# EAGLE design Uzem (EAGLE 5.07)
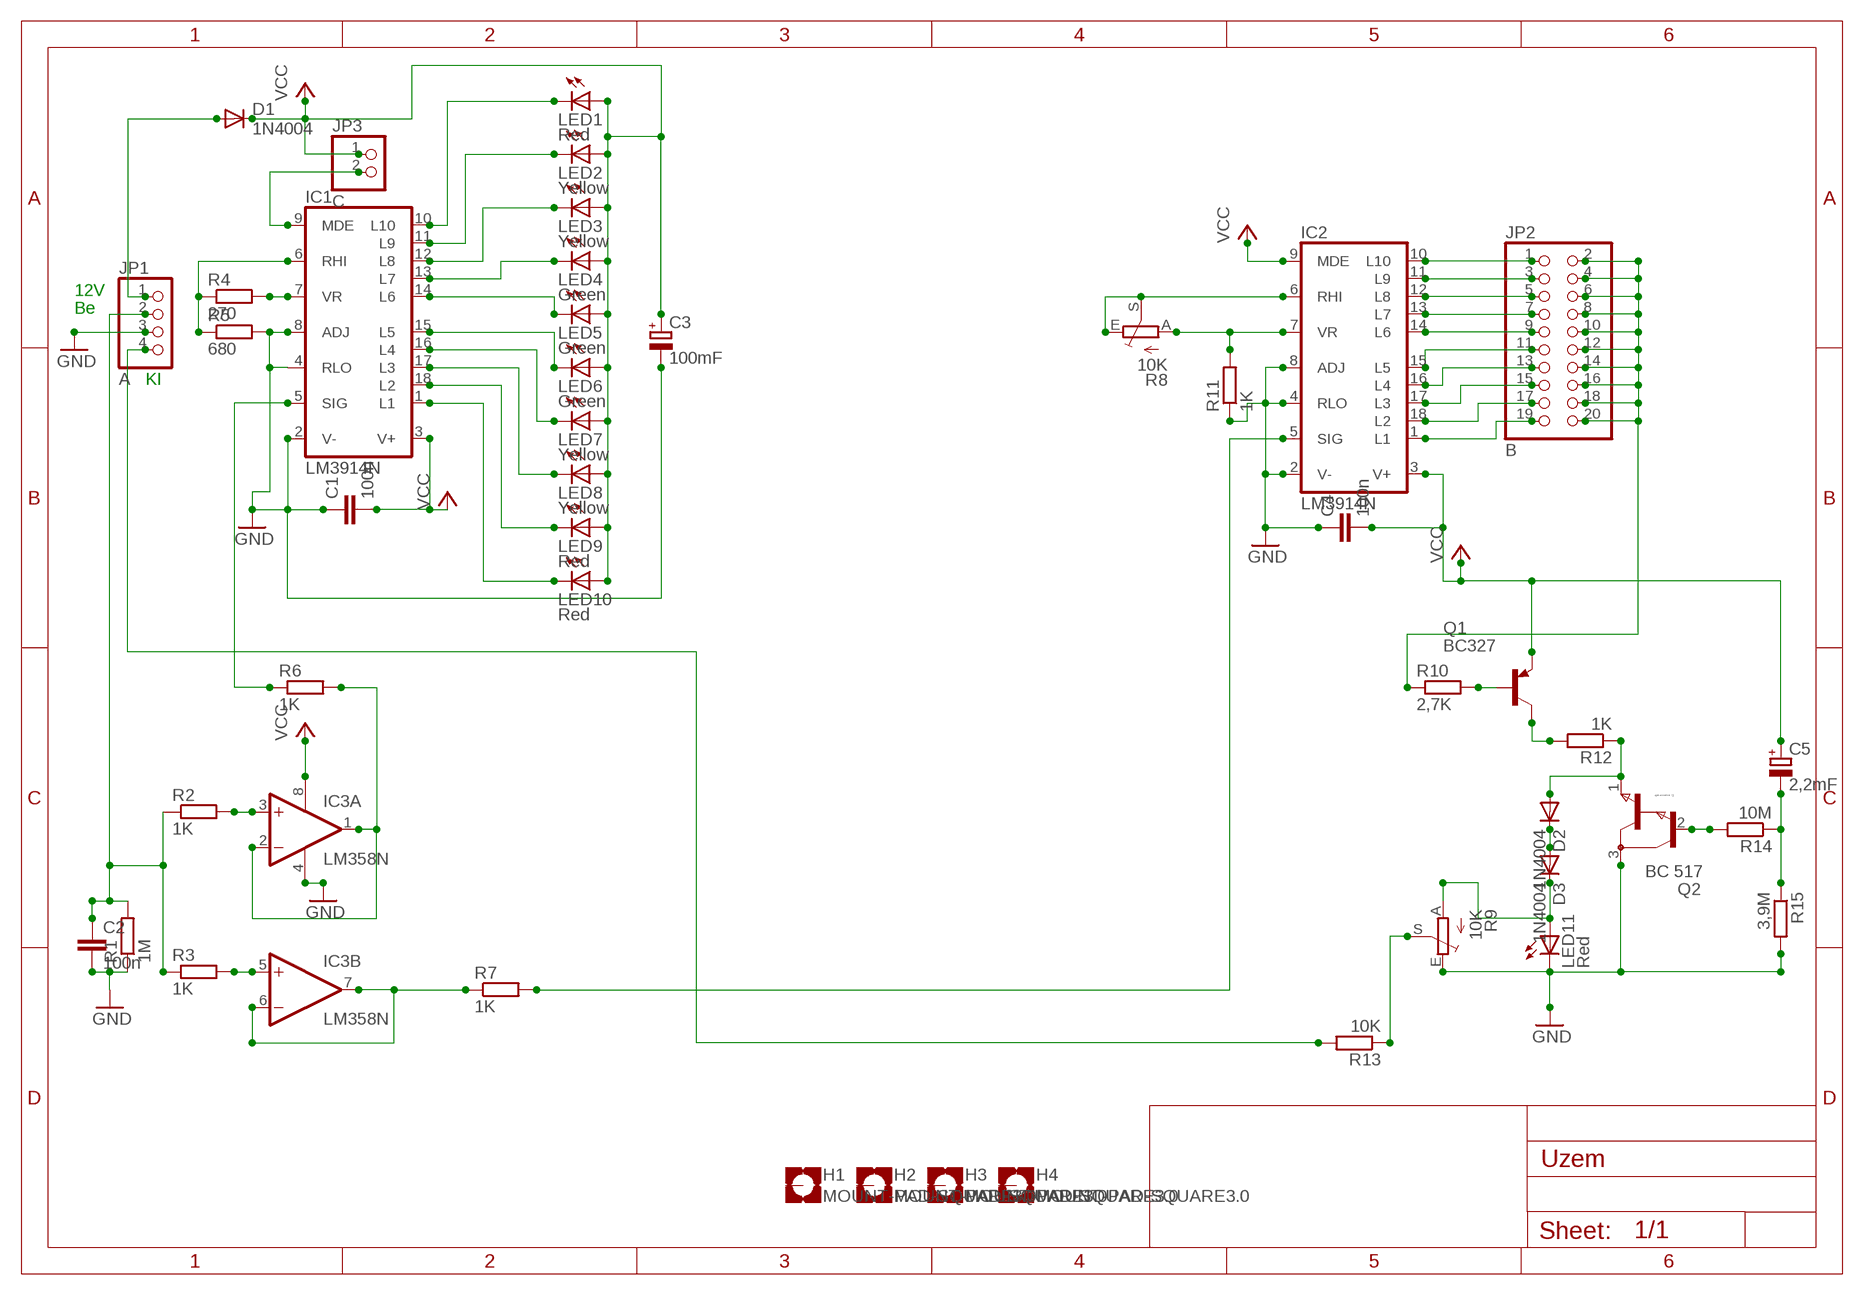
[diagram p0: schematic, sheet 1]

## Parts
C1  100n  C-EU025-025X050  [C025-025X050]
C2  100n  C-EU025-025X050  [C025-025X050]
C3  100mF  CPOL-EUE2,5-6E  [E2,5-6E]
C4  100n  C-EU025-025X050  [C025-025X050]
C5  2,2mF  CPOL-EUE2,5-6E  [E2,5-6E]
D1  1N4004  [DO41-10]
D2  1N4004  [DO41-10]
D3  1N4004  [DO41-10]
H1  MOUNT-PAD-SQUARE3.0  [3,0-PAD-SQUARE]
H2  MOUNT-PAD-SQUARE3.0  [3,0-PAD-SQUARE]
H3  MOUNT-PAD-SQUARE3.0  [3,0-PAD-SQUARE]
H4  MOUNT-PAD-SQUARE3.0  [3,0-PAD-SQUARE]
IC1  LM3914N  [DIL18]
IC2  LM3914N  [DIL18]
IC3  LM358N  [DIL08]
JP1  A  PINHD-1X4  [1X04]
JP2  B  PINHD-2X10  [2X10]
JP3  C  PINHD-1X2  [1X02]
LED1  Red  LED5MM  [LED5MM]
LED2  Yellow  LED5MM  [LED5MM]
LED3  Yellow  LED5MM  [LED5MM]
LED4  Green  LED5MM  [LED5MM]
LED5  Green  LED5MM  [LED5MM]
LED6  Green  LED5MM  [LED5MM]
LED7  Yellow  LED5MM  [LED5MM]
LED8  Yellow  LED5MM  [LED5MM]
LED9  Red  LED5MM  [LED5MM]
LED10  Red  LED5MM  [LED5MM]
LED11  Red  LED5MM  [LED5MM]
Q1  BC327  [TO92]
Q2  BC 517  BC517  [TO92]
R1  1M  R-EU_0204/7  [0204/7]
R2  1K  R-EU_0204/7  [0204/7]
R3  1K  R-EU_0204/7  [0204/7]
R4  270  R-EU_0204/7  [0204/7]
R5  680  R-EU_0204/7  [0204/7]
R6  1K  R-EU_0204/7  [0204/7]
R7  1K  R-EU_0204/7  [0204/7]
R8  10K  TRIM_EU-CA6V  [CA6V]
R9  10K  TRIM_EU-CA6V  [CA6V]
R10  2,7K  R-EU_0204/7  [0204/7]
R11  1K  R-EU_0204/7  [0204/7]
R12  1K  R-EU_0204/7  [0204/7]
R13  10K  R-EU_0204/7  [0204/7]
R14  10M  R-EU_0204/7  [0204/7]
R15  3,9M  R-EU_0204/7  [0204/7]

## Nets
GND: C1.1 C2.2 C3.- C4.1 IC1.2(V-) IC1.4(RLO) IC1.8(ADJ) IC2.2(V-) IC2.4(RLO) IC2.8(ADJ) IC3.4(P:V-) JP1.3 LED11.K(C) Q2.3(C) R1.1 R5.2 R9.E R11.1 R15.2
N$1: IC1.10(L10) LED1.K(C)
N$2: IC1.5(SIG) R6.1
N$3: IC1.11(L9) LED2.K(C)
N$4: IC1.12(L8) LED3.K(C)
N$5: IC1.13(L7) LED4.K(C)
N$6: IC1.14(L6) LED5.K(C)
N$7: IC1.15(L5) LED6.K(C)
N$8: IC1.16(L4) LED7.K(C)
N$9: IC1.17(L3) LED8.K(C)
N$10: IC1.18(L2) LED9.K(C)
N$11: IC1.1(L1) LED10.K(C)
N$12: IC2.5(SIG) R7.2
N$13: C2.1 JP1.2 R1.2 R2.1 R3.1
N$14: JP2.2 JP2.4 JP2.6 JP2.8 JP2.10 JP2.12 JP2.14 JP2.16 JP2.18 JP2.20 R10.1
N$15: IC1.6(RHI) R4.1 R5.1
N$16: IC3.3(A:+IN) R2.2
N$17: IC3.5(B:+IN) R3.2
N$18: IC1.7(VR) R4.2
N$19: IC2.10(L10) JP2.1
N$20: IC2.11(L9) JP2.3
N$21: Q1.2(B) R10.2
N$22: IC2.12(L8) JP2.5
N$23: IC2.13(L7) JP2.7
N$24: IC2.14(L6) JP2.9
N$25: IC2.15(L5) JP2.11
N$26: IC2.16(L4) JP2.13
N$27: IC2.17(L3) JP2.15
N$28: IC2.18(L2) JP2.17
N$29: IC2.1(L1) JP2.19
N$30: IC3.1(A:OUT) IC3.2(A:-IN) R6.2
N$31: D2.C D3.A
N$32: IC3.6(B:-IN) IC3.7(B:OUT) R7.1
N$33: D3.C LED11.A R9.A
N$34: Q1.3(C) R12.2
N$35: D2.A Q2.1(E) R12.1
N$36: R9.S R13.1
N$37: Q2.2(B) R14.2
N$38: IC2.7(VR) R8.A R11.2
N$40: IC1.9(MDE) JP3.2
N$42: JP1.4 R13.2
N$43: C5.- R14.1 R15.1
N$44: IC2.6(RHI) R8.E R8.S
N$45: D1.A JP1.1
VCC: C1.2 C3.+ C4.2 C5.+ D1.C IC1.3(V+) IC2.3(V+) IC2.9(MDE) IC3.8(P:V+) JP3.1 LED1.A LED2.A LED3.A LED4.A LED5.A LED6.A LED7.A LED8.A LED9.A LED10.A Q1.1(E)
Unconnected: H1.B3,0(MOUNT) H2.B3,0(MOUNT) H3.B3,0(MOUNT) H4.B3,0(MOUNT)

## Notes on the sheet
- 12V
- Be
- KI

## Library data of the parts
C1 C2 C4 = rcl:C-EU: CAPACITOR, European symbol
C3 C5 = rcl:CPOL-EU: POLARIZED CAPACITOR, European symbol
D1-D3 = diode-1:1N4004: DIODE
H1-H4 = holes:MOUNT-PAD-SQUARE: MOUNTING PAD, square
IC1 IC2 = linear4:LM3914N: LED DRIVER senses analog voltage levels and drives 10 LEDs
IC3 = linear4:LM358: OP AMP
JP1 = pinhead:PINHD-1X4: PIN HEADER
JP2 = pinhead:PINHD-2X10: PIN HEADER
JP3 = pinhead:PINHD-1X2: PIN HEADER
LED1-LED11 = led:LED: LED
Q1 = transistor-pnp:BC327: PNP Transistor
Q2 = NPN:BC517
R1-R7 R10-R15 = rcl:R-EU_: RESISTOR, European symbol
R8 R9 = pot:TRIM_EU-: POTENTIOMETER

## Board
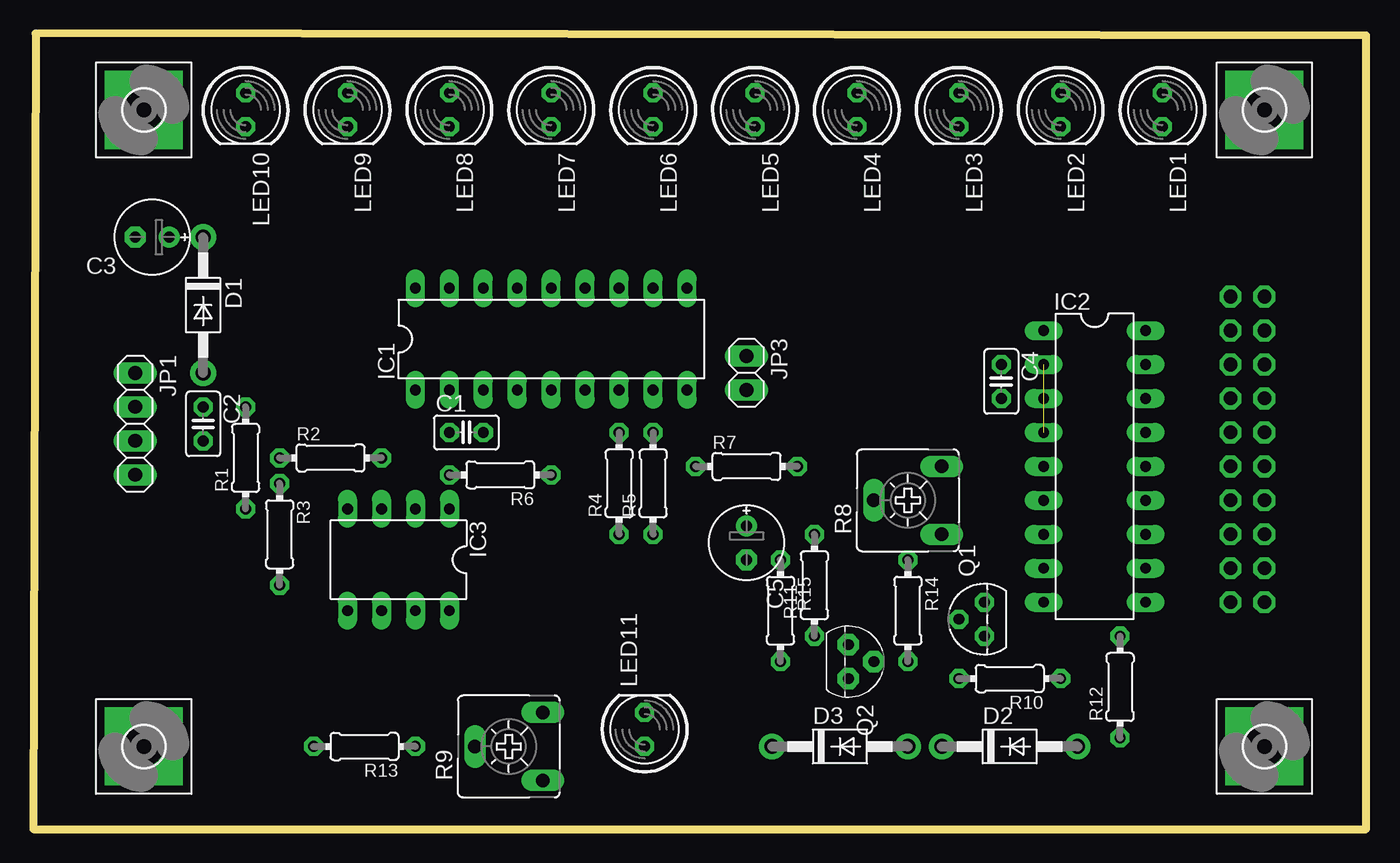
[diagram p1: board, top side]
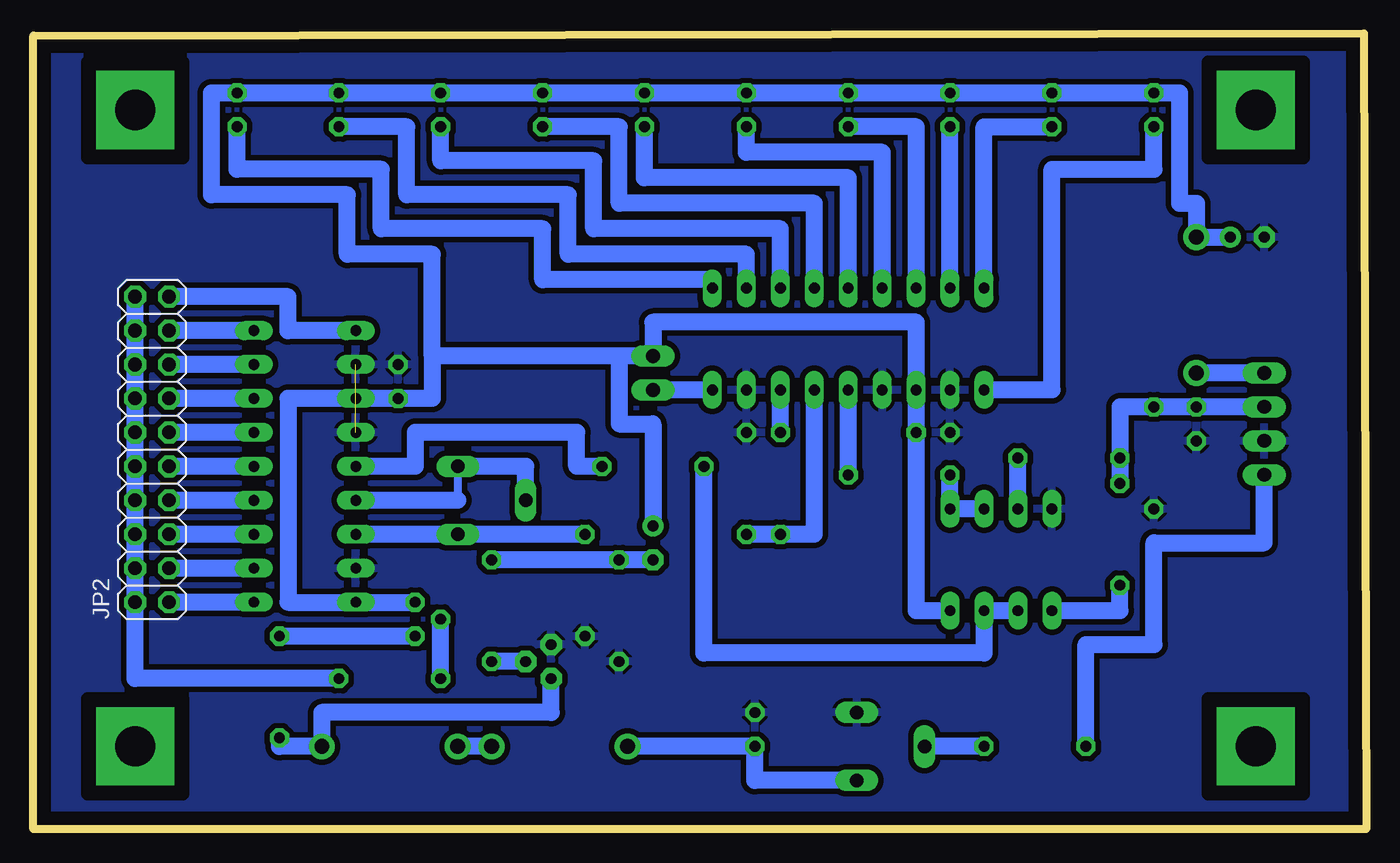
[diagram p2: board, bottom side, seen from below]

Size 99.68 x 59.53 mm. Coordinates in mm from the lower left corner, seen from the top.
Outline: 0,0 99.68,0 99.68,59.36 0.16,59.53 0,0
Copper layers (1*16): Top 0.035mm / dielectric 1.5mm / Bottom 0.035mm
Design rules "default *": minimum track width 16mil, minimum drill 24mil, track to track 16mil, track to pad 16mil, pad to pad 12mil, via to via 16mil, smd to smd 8mil, copper to edge 40mil, drill to drill 16mil, minimum pad ring 12mil, minimum via ring 12mil, stop-mask expansion 4mil, vias tented up to drill 0mil, thermal gap 10mil

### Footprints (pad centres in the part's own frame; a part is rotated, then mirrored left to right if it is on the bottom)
C025-025X050 = drill 0.813 octagon: 1 -1.27,0; 2 1.27,0
E2,5-6E = drill 0.813 pad 1.575 round: + -1.27,0 | drill 0.813 pad 1.575 octagon: - 1.27,0
DO41-10 = drill 1.118 pad 1.93 round: A 5.08,0; C -5.08,0
3,0-PAD-SQUARE = drill 3 pad 5.842 square: B3,0 0,0
DIL18 = drill 0.813 long: 1 -10.16,-3.81; 2 -7.62,-3.81; 3 -5.08,-3.81; 4 -2.54,-3.81; 5 0,-3.81; 6 2.54,-3.81; 7 5.08,-3.81; 8 7.62,-3.81; 9 10.16,-3.81; 10 10.16,3.81; 11 7.62,3.81; 12 5.08,3.81; 13 2.54,3.81; 14 0,3.81; 15 -2.54,3.81; 16 -5.08,3.81; 17 -7.62,3.81; 18 -10.16,3.81
DIL08 = drill 0.813 long: 1 -3.81,-3.81; 2 -1.27,-3.81; 3 1.27,-3.81; 4 3.81,-3.81; 5 3.81,3.81; 6 1.27,3.81; 7 -1.27,3.81; 8 -3.81,3.81
1X04 = drill 1.016 long: 1 -3.81,0; 2 -1.27,0; 3 1.27,0; 4 3.81,0
2X10 = drill 1.016 octagon: 1 -11.43,-1.27; 2 -11.43,1.27; 3 -8.89,-1.27; 4 -8.89,1.27; 5 -6.35,-1.27; 6 -6.35,1.27; 7 -3.81,-1.27; 8 -3.81,1.27; 9 -1.27,-1.27; 10 -1.27,1.27; 11 1.27,-1.27; 12 1.27,1.27; 13 3.81,-1.27; 14 3.81,1.27; 15 6.35,-1.27; 16 6.35,1.27; 17 8.89,-1.27; 18 8.89,1.27; 19 11.43,-1.27; 20 11.43,1.27
1X02 = drill 1.016 long: 1 -1.27,0; 2 1.27,0
LED5MM = drill 0.813 octagon: A -1.27,0; K 1.27,0
TO92 = drill 0.813 octagon: 1 1.27,0; 2 0,1.905; 3 -1.27,0
TO92' = drill 0.813 pad 1.6 octagon: 1 1.27,0; 2 0,1.905; 3 -1.27,0
0204/7 = drill 0.813 octagon: 1 -3.81,0; 2 3.81,0
CA6V = drill 1.016 long: A -2.54,-2.54; E 2.54,-2.54; S 0,2.54

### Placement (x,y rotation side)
C1  32.38,29.68 0 top
C2  12.69,30.32 270 top
C3  8.88,44.29 180 top
C4  72.39,33.49 270 top
C5  53.34,21.43 270 top
D1  12.69,39.2 270 top
D2  73.02,6.18 0 top
D3  60.32,6.18 0 top
H1  8.25,53.81 0 top
H2  8.25,6.18 0 top
H3  92.07,6.18 0 top
H4  92.07,53.81 0 top
IC1  38.73,36.66 0 top
IC2  79.37,27.14 270 top
IC3  27.3,20.16 180 top
JP1  7.62,30.32 270 top
JP2  90.8,28.41 90 bottom
JP3  53.34,34.12 270 top
LED1  84.45,53.81 270 top
LED2  76.83,53.81 270 top
LED3  69.21,53.81 270 top
LED4  61.59,53.81 270 top
LED5  53.97,53.81 270 top
LED6  46.35,53.81 270 top
LED7  38.73,53.81 270 top
LED8  31.11,53.81 270 top
LED9  23.49,53.81 270 top
LED10  15.87,53.81 270 top
LED11  45.71,7.46 90 top
Q1  71.12,15.71 90 top
Q2  BC 517  [TO92']  60.95,12.54 270 top
R1  15.87,27.78 90 top
R2  22.22,27.78 0 top
R3  18.41,22.06 270 top
R4  43.81,25.87 90 top
R5  46.35,25.87 90 top
R6  34.92,26.51 180 top
R7  53.34,27.14 0 top
R8  65.4,24.6 90 top
R9  35.55,6.18 90 top
R10  73.02,11.27 180 top
R11  58.41,18.25 90 top
R12  81.28,10.63 90 top
R13  24.76,6.18 180 top
R14  65.4,16.35 270 top
R15  55.88,16.35 270 top

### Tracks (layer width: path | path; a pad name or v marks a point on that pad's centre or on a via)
GND  (1 unrouted)
  pour Bottom (isolate 0.305): 0.63,58.89 99.06,58.89 99.06,0.47 0.63,0.47
N$1
  Bottom 0.61: IC1.10 48.89,41.11
  Bottom 1.27: 48.89,41.11 61.59,41.11 61.59,44.92 73.66,44.92 73.66,49.37 84.45,49.37 LED1.K
N$2
  Bottom 1.27: R6.1 IC1.5
N$3
  Bottom 1.27: IC1.11 46.35,43.02 59.68,43.02 59.68,47.46 71.75,47.46 71.75,52.54 LED2.K
N$4
  Bottom 1.27: IC1.12 43.81,44.92 57.78,44.92 57.78,50 69.21,50 LED3.K
N$5
  Bottom 1.27: IC1.13 41.27,46.83 55.88,46.83 55.88,52.54 LED4.K
N$6
  Bottom 1.27: IC1.14 38.73,48.73 53.97,48.73 LED5.K
N$7
  Bottom 1.27: IC1.15 36.19,50.63 46.35,50.63 LED6.K
N$8
  Bottom 1.27: IC1.16 33.65,52.54 LED7.K
N$9
  Bottom 1.27: LED8.K 31.11,41.11 IC1.17
N$10
  Bottom 1.27: IC1.18 28.57,52.54 LED9.K
N$11
  Bottom 1.27: IC1.1 23.49,32.86 23.49,49.37 15.87,49.37 LED10.K
N$12
  Bottom 1.27: IC2.5 71.12,27.14 71.12,29.68 59.05,29.68 59.05,27.14 R7.2
N$13
  Bottom 1.27: R3.1 R2.1 18.41,31.59 R1.2 C2.1 JP1.2
N$14
  Bottom 1.27: JP2.20 JP2.18 JP2.16 JP2.14 JP2.12 JP2.10 JP2.8 JP2.6 JP2.4 JP2.2 92.07,11.27 R10.1
N$15
  Bottom 1.27: R5.1 R4.1 41.27,22.06 IC1.6
N$16
  Bottom 1.27: IC3.3 R2.2
N$17
  Bottom 1.27: R3.2 18.41,16.35 IC3.5
N$18
  Bottom 1.27: R4.2 IC1.7
N$19
  Bottom 1.27: IC2.10 JP2.1
N$20
  Bottom 1.27: IC2.11 JP2.3
N$21
  Bottom 1.27: R10.2 Q1.2
N$22
  Bottom 1.27: IC2.12 JP2.5
N$23
  Bottom 1.27: IC2.13 JP2.7
N$24
  Bottom 1.27: IC2.14 JP2.9
N$25
  Bottom 1.27: IC2.15 JP2.11
N$26
  Bottom 1.27: IC2.16 JP2.13
N$27
  Bottom 1.27: IC2.17 JP2.15
N$28
  Bottom 1.27: IC2.18 JP2.17
N$29
  Bottom 1.27: IC2.1 80.64,37.3 80.64,39.84 JP2.19
N$30
  Bottom 1.27: IC3.2 IC3.1 R6.2
N$31
  Bottom 1.27: D3.A D2.C
N$32
  Bottom 1.27: IC3.6 IC3.7 28.57,13.17 49.52,13.17 R7.1
N$33
  Bottom 1.27: D3.C LED11.A 45.71,3.65 R9.A
N$34
  Bottom 1.27: Q1.3 R12.2
N$35
  Bottom 1.27: R12.1 81.28,6.18 D2.A 78.1,8.73 60.95,8.73 Q2.1
N$36
  Bottom 1.27: R13.1 R9.S
N$37
  Bottom 1.27: Q2.2 R14.2
N$38
  Bottom 1.27: IC2.7 R8.A R11.2
N$39
  pour Bottom: -0.01,59.52 99.69,59.52 99.69,-0.17 -0.01,-0.17
N$40
  Bottom 1.27: IC1.9 JP3.2
N$41
  pour Bottom (isolate 0.305): -0.01,59.52 0.63,59.52
N$42
  Bottom 1.27: R13.2 20.95,13.81 15.87,13.81 15.87,21.43 7.62,21.43 JP1.4
N$43
  Bottom 1.27: R14.1 R15.1 C5.-
N$44
  Bottom 0.61: R8.E 67.94,24.6
  Bottom 1.27: 67.94,24.6 IC2.6 | R8.E 62.86,27.14 R8.S
N$45
  Bottom 1.27: JP1.1 D1.A
VCC
  Bottom 1.27: Q1.1 IC2.9 80.64,16.98 80.64,32.22 IC2.3 C4.2 69.84,32.22 69.84,35.4 | C3.+ D1.C 12.69,46.83 13.96,46.83 13.96,55.08 LED10.A LED9.A LED8.A LED7.A LED6.A LED5.A LED4.A LED3.A LED2.A LED1.A 86.36,55.08 86.36,47.46 76.2,47.46 76.2,43.02 69.84,43.02 69.84,35.4 | 55.88,35.4 JP3.1 53.34,37.94 33.65,37.94 IC1.3 C1.2 33.65,16.35 IC3.8 | 55.88,35.4 69.84,35.4 | C5.+ 53.34,30.32 55.88,30.32 55.88,35.4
